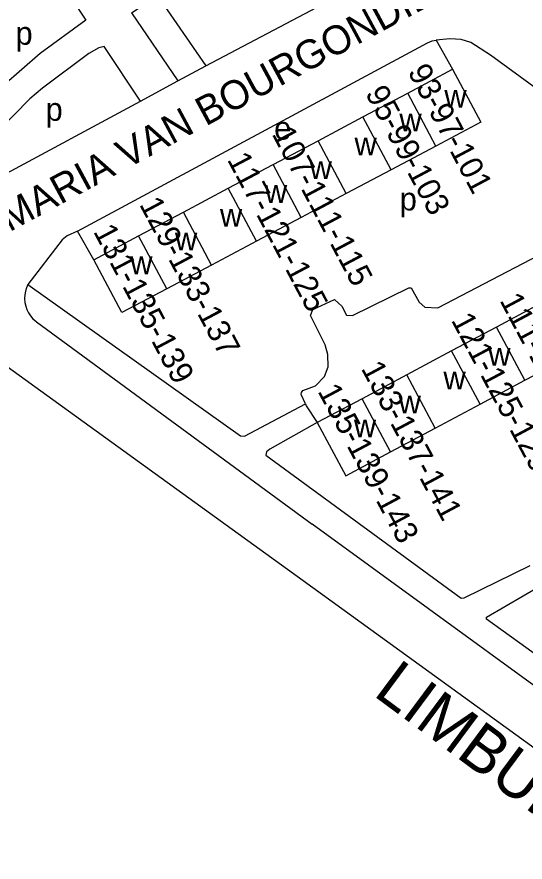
# Model space of a CAD drawing. Extents: x 159700 to 161346, y 381730 to 382922.
# Drawn here: x 159886.3 to 159974.4, y 382258.8 to 382405.4 of the extents above; entities that cross this region are included whole.
import ezdxf

# ---------------------------------------------------------------- set-up
doc = ezdxf.new("R2010")
doc.units = 0
for name, color, linetype in [('BLT_Basislijn', 7, 'Continuous'), ('BLT_Bebouwing', 7, 'Continuous'), ('BLT_Centroide', 7, 'Continuous'), ('BLT_Huisnummer_reeks', 7, 'Continuous'), ('BLT_Onderverdeling_panden', 7, 'Continuous'), ('BLT_Straatnaam', 7, 'Continuous'), ('BLT_Straatnaam_hoofdweg', 7, 'Continuous')]:
    doc.layers.add(name, color=color, linetype=linetype)

msp = doc.modelspace()

# ---------------------------------------------------------------- linework, layer by layer
at = {"layer": 'BLT_Basislijn'}
for p, q in [((159919.07, 382396.91), (159953.34, 382415)), ((159892.22, 382414.08), (159898.27, 382404.83)), ((159906.19, 382406.1), (159914.24, 382394.31)), ((159959, 382401.34), (159961.85, 382396.3)), ((159914.24, 382394.31), (159919.07, 382396.91)), ((159907.74, 382390.8), (159914.24, 382394.31)), ((159839.77, 382377.24), (159935.92, 382307.64)), ((159899.64, 382363.28), (159896.86, 382368.25)), ((159889.73, 382352.49), (159937.53, 382317.42)), ((160016.31, 382259.98), (159937.53, 382317.42)), ((159935.92, 382307.64), (159998.26, 382262.49))]:
    msp.add_line(p, q, dxfattribs=at)
for points in [[(159906.19, 382406.1), (159910.7, 382409.1), (159919.07, 382396.91)], [(159898.27, 382404.83), (159890.38, 382399.05), (159884.01, 382393.5), (159880.31, 382389.83), (159873.26, 382380.75), (159868.59, 382373.57)], [(159896.86, 382368.25), (159957.5, 382400.91), (159958.27, 382401.25), (159959, 382401.34)], [(159994.32, 382379.81), (159968.39, 382398.77), (159964.97, 382400.93), (159963.32, 382401.44), (159961.34, 382401.6), (159959, 382401.34)], [(159907.74, 382390.8), (159901.46, 382400.23), (159900.55, 382400.05), (159898.79, 382399.04), (159890.77, 382393.01), (159888.58, 382391.17), (159882.9, 382385.47), (159881.17, 382383.57), (159872.29, 382370.87)], [(159876.23, 382368.08), (159883.01, 382377.49), (159907.74, 382390.8)], [(159896.86, 382368.25), (159895.02, 382367.45), (159894.19, 382366.72), (159888.25, 382359.01)], [(159936.32, 382338.3), (159935.6, 382339.92), (159935.68, 382340.27), (159935.88, 382340.62), (159938.1, 382341.43), (159939.62, 382343.02), (159940.29, 382344.7), (159940.24, 382346.84), (159939.75, 382348.52), (159937.24, 382353.58), (159937.62, 382354.62), (159941.37, 382356.39), (159942.66, 382355.2), (159943.44, 382353.64), (159944.49, 382353.58), (159954.25, 382358.4), (159954.63, 382358.4), (159956.02, 382355.92), (159957.02, 382355.06), (159959.28, 382354.94), (159984.78, 382368.21)], [(159888.25, 382359.01), (159887.99, 382358.42), (159887.81, 382357.8), (159887.7, 382357.17), (159887.67, 382356.53), (159887.73, 382355.89), (159887.86, 382355.25), (159888.07, 382354.65), (159888.35, 382354.07), (159888.7, 382353.53), (159889.12, 382353.04), (159889.6, 382352.6), (159889.73, 382352.49)], [(159888.25, 382359.01), (159925.1, 382332.74), (159925.79, 382332.67), (159936.32, 382338.3)], [(159936.32, 382338.3), (159936.48, 382337.95), (159938.38, 382335.04)], [(159938.38, 382335.04), (159930.16, 382330.42), (159929.6, 382329.98), (159929.45, 382329.41), (159963.32, 382304.6), (159963.86, 382304.63), (159975.3, 382310.27)], [(160013.97, 382282.21), (160004.02, 382276.68), (160001.8, 382276.41), (159967.72, 382300.96), (159967.73, 382301.29), (159977.24, 382306.84)]]:
    msp.add_lwpolyline(points, dxfattribs=at)
at = {"layer": 'BLT_Bebouwing'}
for p, q in [((159954.08, 382392.18), (159961.85, 382396.3)), ((159946.3, 382388.05), (159954.08, 382392.18)), ((159938.52, 382383.92), (159946.3, 382388.05)), ((159930.74, 382379.8), (159938.52, 382383.92)), ((159958.95, 382382.99), (159951.17, 382378.86)), ((159922.97, 382375.67), (159930.74, 382379.8)), ((159951.17, 382378.86), (159943.4, 382374.74)), ((159915.19, 382371.54), (159922.97, 382375.67)), ((159943.4, 382374.74), (159935.62, 382370.61)), ((159907.41, 382367.41), (159915.19, 382371.54)), ((159935.62, 382370.61), (159927.84, 382366.48)), ((159899.64, 382363.28), (159907.41, 382367.41)), ((159927.84, 382366.48), (159920.06, 382362.35)), ((159920.06, 382362.35), (159912.29, 382358.23)), ((159977.19, 382355.75), (159969.43, 382351.61)), ((159969.43, 382351.61), (159961.67, 382347.47)), ((159961.67, 382347.47), (159953.9, 382343.32)), ((159974.36, 382342.37), (159982.12, 382346.51)), ((159953.9, 382343.32), (159946.14, 382339.18)), ((159966.6, 382338.22), (159974.36, 382342.37)), ((159946.14, 382339.18), (159938.38, 382335.04)), ((159958.84, 382334.08), (159966.6, 382338.22)), ((159951.07, 382329.94), (159958.84, 382334.08))]:
    msp.add_line(p, q, dxfattribs=at)
for points in [[(159961.85, 382396.3), (159966.73, 382387.12), (159958.95, 382382.99)], [(159912.29, 382358.23), (159904.51, 382354.1), (159899.64, 382363.28)], [(159938.38, 382335.04), (159943.31, 382325.8), (159951.07, 382329.94)]]:
    msp.add_lwpolyline(points, dxfattribs=at)
at = {"layer": 'BLT_Onderverdeling_panden'}
for p, q in [((159958.95, 382382.99), (159954.08, 382392.18)), ((159951.17, 382378.86), (159946.3, 382388.05)), ((159943.4, 382374.74), (159938.52, 382383.92)), ((159935.62, 382370.61), (159930.74, 382379.8)), ((159927.84, 382366.48), (159922.97, 382375.67)), ((159920.06, 382362.35), (159915.19, 382371.54)), ((159912.29, 382358.23), (159907.41, 382367.41)), ((159974.36, 382342.37), (159969.43, 382351.61)), ((159966.6, 382338.22), (159961.67, 382347.47)), ((159958.84, 382334.08), (159953.9, 382343.32)), ((159951.07, 382329.94), (159946.14, 382339.18))]:
    msp.add_line(p, q, dxfattribs=at)

# ---------------------------------------------------------------- texts
at = {"layer": 'BLT_Centroide'}
for s, p in [('p', (159886.09, 382400.56)), ('w', (159960.41, 382389.64)), ('p', (159891.3, 382387.37)), ('w', (159952.62, 382385.52)), ('e', (159930.91, 382384.1)), ('w', (159944.84, 382381.39)), ('w', (159937.06, 382377.27)), ('w', (159929.3, 382373.14)), ('p', (159952.67, 382371.82)), ('w', (159921.52, 382369.02)), ('w', (159913.73, 382364.89)), ('w', (159905.97, 382360.77)), ('w', (159968.02, 382344.91)), ('w', (159960.25, 382340.78)), ('w', (159952.48, 382336.62)), ('w', (159944.73, 382332.5))]:
    msp.add_text(s, height=4, dxfattribs=at).set_placement(p)
at = {"layer": 'BLT_Huisnummer_reeks'}
for s, rotation, p in [('93-97-101', 297.9577, (159953.99, 382395.91)), ('95-99-103', 297.9577, (159946.63, 382392.17)), ('107-111-115', 297.9574, (159930.44, 382385.11)), ('117-121-125', 297.9574, (159922.7, 382380.65)), ('129-133-137', 297.9574, (159907.47, 382372.9)), ('131-135-139', 297.9574, (159899.5, 382368.18)), ('111-115-119', 298.0857, (159969.91, 382356.24)), ('121-125-129', 298.0857, (159961.51, 382352.81)), ('133-137-141', 298.0899, (159945.9, 382344.44)), ('135-139-143', 298.0796, (159938.38, 382340.49))]:
    msp.add_text(s, height=4, rotation=rotation, dxfattribs=at).set_placement(p)
at = {"layer": 'BLT_Straatnaam'}
msp.add_text('MARIA VAN BOURGONDIELAAN', height=5, rotation=28.3112, dxfattribs=at).set_placement((159885.03, 382368.04))
at = {"layer": 'BLT_Straatnaam_hoofdweg'}
msp.add_text('LIMBURGLAAN', height=7.9999, rotation=323.4093, dxfattribs=at).set_placement((159947.9, 382287.83))

doc.saveas('drawing.dxf')
